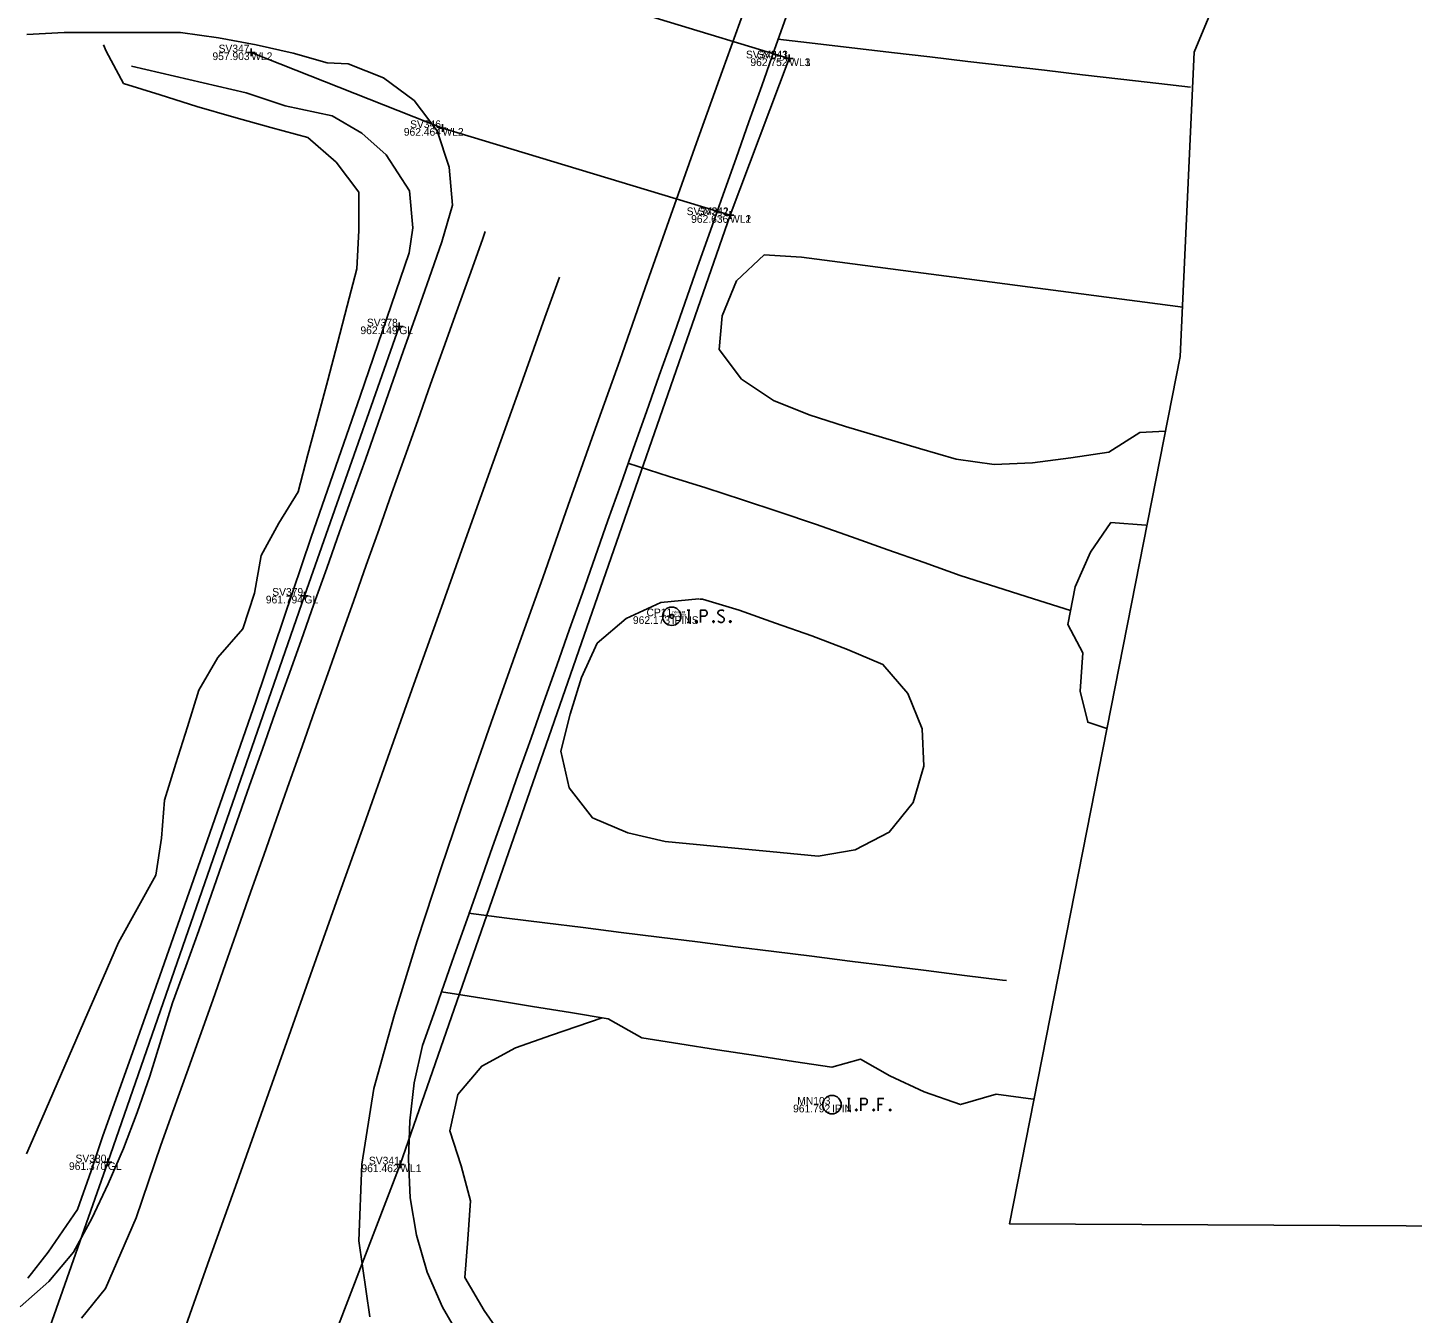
# Model space of a CAD drawing. Extents: x 2262025 to 2264532, y 740981 to 742724.
# Drawn here: x 2263322.3 to 2263502.4, y 742430.2 to 742597.4 of the extents above; entities that cross this region are included whole.
import ezdxf

# ---------------------------------------------------------------- set-up
doc = ezdxf.new("R2010")
doc.units = 0
for name, color, linetype in [('DT_X_Break_Line', 7, 'Continuous'), ('GE_X_Alignment_100_Cardinal_Points', 7, 'Continuous'), ('GE_X_Alignment_100_Curve_Data', 7, 'Continuous'), ('HY_X_Spring_Cells', 7, 'Continuous'), ('PV_X_Driveway', 7, 'Continuous'), ('RS_Raster1', 7, 'Continuous'), ('RW_X_CL', 7, 'Continuous'), ('RW_X_CL_1000_Bearings', 7, 'Continuous'), ('RW_X_CL_1000_Distances', 7, 'Continuous'), ('RW_X_CL_1000_Stations', 7, 'Continuous'), ('RW_X_CL_100_Bearings', 7, 'Continuous'), ('RW_X_CL_100_Cardinal_Points', 7, 'Continuous'), ('RW_X_CL_500_Curve_Data', 7, 'Continuous'), ('SC_Scratch4', 7, 'Continuous'), ('SV_X_Control_Cells_Found', 7, 'Continuous'), ('SV_X_Text_Comment', 7, 'Continuous'), ('SV_X_Text_Elevation', 7, 'Continuous'), ('TopoDOT Temp', 7, 'Continuous'), ('UT_X_Gas', 7, 'Continuous'), ('UT_X_Water', 7, 'Continuous')]:
    doc.layers.add(name, color=color, linetype=linetype)

msp = doc.modelspace()

# ---------------------------------------------------------------- linework, layer by layer
at = {"layer": 'DT_X_Break_Line'}
for points in [[(2263419.9, 742595.91), (2263424.75, 742595.35), (2263434.68, 742594.19), (2263439.65, 742593.62), (2263444.62, 742593.04), (2263449.58, 742592.47), (2263454.55, 742591.89), (2263459.52, 742591.31), (2263464.48, 742590.74), (2263469.45, 742590.16), (2263473.55, 742589.68)], [(2263400.39, 742540.76), (2263405.76, 742539.06), (2263410.53, 742537.55), (2263415.29, 742536.02), (2263420.03, 742534.43), (2263424.77, 742532.84), (2263429.49, 742531.2), (2263434.2, 742529.52), (2263438.91, 742527.84), (2263443.62, 742526.17), (2263448.38, 742524.64), (2263453.15, 742523.13), (2263457.95, 742521.6)], [(2263379.67, 742482.22), (2263384.63, 742481.6), (2263389.59, 742480.98), (2263394.55, 742480.36), (2263399.51, 742479.74), (2263404.47, 742479.11), (2263409.43, 742478.49), (2263414.39, 742477.87), (2263419.35, 742477.25), (2263424.31, 742476.63), (2263429.27, 742476.01), (2263434.24, 742475.39), (2263439.2, 742474.77), (2263444.16, 742474.15), (2263449.12, 742473.52), (2263449.61, 742473.46)]]:
    msp.add_lwpolyline(points, dxfattribs=at)
at = {"layer": 'GE_X_Alignment_100_Cardinal_Points'}
msp.add_lwpolyline([(2263322.32, 742434.75), (2263324.98, 742438.15), (2263328.8, 742443.67), (2263330.57, 742448.73), (2263332.08, 742453.28), (2263335.94, 742464.06), (2263339.49, 742474.09), (2263345.66, 742491.66), (2263351.99, 742509.81), (2263359.2, 742531.16), (2263365.57, 742549.5), (2263371.94, 742568.15), (2263372.4, 742571.39), (2263371.98, 742576.22), (2263368.93, 742580.89), (2263365.76, 742583.71), (2263361.94, 742585.94), (2263355.81, 742587.26), (2263350.72, 742588.96), (2263335.82, 742592.43)], dxfattribs=at)
at = {"layer": 'GE_X_Alignment_100_Curve_Data'}
for points in [[(2263321.32, 742431.03), (2263325.07, 742434.33), (2263328.26, 742438.16), (2263330.65, 742442.54), (2263332.8, 742447.05), (2263334.79, 742451.64), (2263336.54, 742456.32), (2263338.21, 742461.03), (2263339.67, 742465.81), (2263341.16, 742470.59), (2263342.87, 742475.28), (2263344.57, 742479.99), (2263346.22, 742484.71), (2263347.88, 742489.42), (2263349.54, 742494.14), (2263351.19, 742498.86), (2263352.85, 742503.58), (2263354.52, 742508.29), (2263356.2, 742513), (2263357.87, 742517.71), (2263359.55, 742522.42), (2263361.22, 742527.13), (2263362.89, 742531.85), (2263364.57, 742536.56), (2263366.24, 742541.27), (2263367.89, 742545.99), (2263369.55, 742550.7), (2263371.21, 742555.42), (2263372.87, 742560.14), (2263374.52, 742564.86), (2263376.2, 742569.57), (2263377.56, 742574.33), (2263377.13, 742579.29), (2263375.58, 742584), (2263372.59, 742587.94), (2263368.59, 742590.9), (2263364.02, 742592.72), (2263361.27, 742592.87)], [(2263378.8, 742426.67), (2263376.28, 742430.99), (2263374.29, 742435.54), (2263372.9, 742440.34), (2263372.06, 742445.23), (2263371.85, 742450.23), (2263372.01, 742455.21), (2263372.59, 742460.17), (2263373.69, 742465.02), (2263375.34, 742469.74), (2263376.13, 742472.02)]]:
    msp.add_lwpolyline(points, dxfattribs=at)
at = {"layer": 'PV_X_Driveway'}
msp.add_lwpolyline([(2263322.19, 742596.54), (2263327.07, 742596.78), (2263332.18, 742596.78), (2263337.18, 742596.78), (2263342.18, 742596.78), (2263347.13, 742596.12), (2263352.04, 742595.19), (2263356.83, 742594.1), (2263361.27, 742592.87)], dxfattribs=at)
at = {"layer": 'RS_Raster1'}
msp.add_lwpolyline([(2263811.08, 742440.01), (2263450.03, 742441.81), (2263472.22, 742554.63), (2263474.02, 742594.23), (2263511.21, 742683.65), (2263410.45, 742724.45), (2263373.87, 742626.04), (2263193.94, 742588.23), (2263081.19, 742567.23), (2263085.99, 742531.22), (2263114.18, 742392.6), (2262376.34, 742066.06)], dxfattribs=at)
at = {"layer": 'RW_X_CL_1000_Bearings'}
msp.add_line((2263406.09, 742520.86), (2263406.09, 742520.86), dxfattribs=at)
msp.add_line((2263406.09, 742520.86), (2263406.09, 742520.86), dxfattribs=at)
msp.add_line((2263406.09, 742520.86), (2263406.09, 742520.86), dxfattribs=at)
at = {"layer": 'RW_X_CL_1000_Distances'}
for points in [[(2263366.8, 742429.72), (2263365.41, 742439.61), (2263365.76, 742449.58), (2263367.32, 742459.44), (2263370.03, 742469.07), (2263372.98, 742478.62), (2263376.11, 742488.12), (2263379.31, 742497.59), (2263382.6, 742507.04), (2263385.95, 742516.46), (2263389.3, 742525.88), (2263392.63, 742535.31), (2263395.97, 742544.74), (2263399.34, 742554.15), (2263402.64, 742563.59), (2263405.97, 742573.02), (2263409.31, 742582.44), (2263412.71, 742591.85), (2263416.07, 742601.27)], [(2263329.31, 742429.55), (2263332.46, 742433.43), (2263334.44, 742438.03), (2263336.41, 742442.62), (2263338.03, 742447.35), (2263339.65, 742452.08), (2263341.34, 742456.78), (2263343.02, 742461.49), (2263344.7, 742466.2), (2263346.39, 742470.91), (2263348.04, 742475.63), (2263349.7, 742480.34), (2263351.36, 742485.06), (2263353.02, 742489.78), (2263354.67, 742494.49), (2263356.33, 742499.21), (2263358, 742503.92), (2263359.67, 742508.64), (2263361.34, 742513.35), (2263363.01, 742518.06), (2263364.68, 742522.78), (2263366.35, 742527.49), (2263368.02, 742532.2), (2263369.69, 742536.92), (2263371.37, 742541.62), (2263373.05, 742546.33), (2263374.73, 742551.04), (2263376.42, 742555.75), (2263378.1, 742560.46), (2263379.78, 742565.16), (2263381.46, 742569.87), (2263381.84, 742570.92)]]:
    msp.add_lwpolyline(points, dxfattribs=at)
at = {"layer": 'RW_X_CL_1000_Stations'}
msp.add_line((2263406.09, 742520.86), (2263406.09, 742520.86), dxfattribs=at)
msp.add_line((2263406.09, 742520.86), (2263406.09, 742520.86), dxfattribs=at)
msp.add_line((2263406.09, 742520.86), (2263406.09, 742520.86), dxfattribs=at)
msp.add_circle((2263406.09, 742520.86), 0.25, dxfattribs=at)
msp.add_circle((2263406.09, 742520.86), 0.25, dxfattribs=at)
msp.add_circle((2263406.09, 742520.86), 0.25, dxfattribs=at)
at = {"layer": 'RW_X_CL_100_Bearings'}
for points in [[(2263408.11, 742521.67), (2263408.46, 742521.67)], [(2263408.29, 742520.07), (2263408.29, 742521.67)], [(2263409.85, 742520.07), (2263409.85, 742521.67), (2263410.38, 742521.67), (2263410.44, 742521.65), (2263410.51, 742521.63), (2263410.55, 742521.6), (2263410.58, 742521.58), (2263410.62, 742521.51), (2263410.66, 742521.45), (2263410.68, 742521.35), (2263410.68, 742521.2), (2263410.67, 742521.15), (2263410.65, 742521.07), (2263410.6, 742520.99), (2263410.56, 742520.95), (2263410.52, 742520.92), (2263410.47, 742520.9), (2263410.38, 742520.88), (2263409.85, 742520.88)], [(2263412.86, 742521.55), (2263412.84, 742521.58), (2263412.81, 742521.6), (2263412.71, 742521.64), (2263412.59, 742521.67), (2263412.5, 742521.67), (2263412.46, 742521.67), (2263412.32, 742521.63), (2263412.2, 742521.55), (2263412.12, 742521.45), (2263412.1, 742521.35), (2263412.1, 742521.28), (2263412.12, 742521.17), (2263412.21, 742521.09), (2263412.82, 742520.71), (2263412.87, 742520.66), (2263412.89, 742520.61), (2263412.92, 742520.53), (2263412.92, 742520.46), (2263412.91, 742520.38), (2263412.89, 742520.33), (2263412.87, 742520.27), (2263412.85, 742520.22), (2263412.83, 742520.18), (2263412.79, 742520.14), (2263412.76, 742520.12), (2263412.72, 742520.09), (2263412.68, 742520.08), (2263412.59, 742520.07), (2263412.43, 742520.07), (2263412.33, 742520.09), (2263412.19, 742520.18), (2263412.1, 742520.25)], [(2263408.11, 742520.07), (2263408.46, 742520.07)], [(2263409.25, 742520.28), (2263409.3, 742520.28), (2263409.33, 742520.25), (2263409.37, 742520.2), (2263409.37, 742520.14), (2263409.33, 742520.09), (2263409.3, 742520.07), (2263409.25, 742520.07), (2263409.21, 742520.09), (2263409.18, 742520.14), (2263409.18, 742520.2), (2263409.21, 742520.25), (2263409.25, 742520.28)], [(2263411.49, 742520.28), (2263411.55, 742520.28), (2263411.58, 742520.25), (2263411.62, 742520.2), (2263411.62, 742520.14), (2263411.58, 742520.09), (2263411.55, 742520.07), (2263411.49, 742520.07), (2263411.46, 742520.09), (2263411.43, 742520.14), (2263411.43, 742520.2), (2263411.46, 742520.25), (2263411.49, 742520.28)], [(2263413.68, 742520.28), (2263413.73, 742520.28), (2263413.76, 742520.25), (2263413.8, 742520.2), (2263413.8, 742520.14), (2263413.76, 742520.09), (2263413.73, 742520.07), (2263413.68, 742520.07), (2263413.64, 742520.09), (2263413.61, 742520.14), (2263413.61, 742520.2), (2263413.64, 742520.25), (2263413.68, 742520.28)]]:
    msp.add_lwpolyline(points, dxfattribs=at)
msp.add_circle((2263406.09, 742520.86), 1.2, dxfattribs=at)
at = {"layer": 'RW_X_CL_100_Cardinal_Points'}
for p, q in [((2263350.9, 742594.21), (2263351.9, 742594.21)), ((2263351.4, 742594.71), (2263351.4, 742593.71)), ((2263351.4, 742594.21), (2263351.4, 742594.21)), ((2263420.88, 742593.43), (2263421.88, 742593.43)), ((2263420.88, 742593.43), (2263421.88, 742593.43)), ((2263421.38, 742593.93), (2263421.38, 742592.93)), ((2263421.38, 742593.93), (2263421.38, 742592.93)), ((2263421.38, 742593.43), (2263421.38, 742593.43)), ((2263421.38, 742593.43), (2263421.38, 742593.43)), ((2263376.27, 742584.87), (2263376.27, 742583.87)), ((2263375.77, 742584.37), (2263376.77, 742584.37)), ((2263376.27, 742584.37), (2263376.27, 742584.37)), ((2263413.17, 742573.04), (2263414.17, 742573.04)), ((2263413.17, 742573.04), (2263414.17, 742573.04)), ((2263413.67, 742573.54), (2263413.67, 742572.54)), ((2263413.67, 742573.54), (2263413.67, 742572.54)), ((2263413.67, 742573.04), (2263413.67, 742573.04)), ((2263413.67, 742573.04), (2263413.67, 742573.04)), ((2263370.15, 742558.56), (2263371.15, 742558.56)), ((2263370.65, 742559.06), (2263370.65, 742558.06)), ((2263370.65, 742558.56), (2263370.65, 742558.56)), ((2263357.82, 742523.53), (2263358.82, 742523.53)), ((2263358.32, 742524.03), (2263358.32, 742523.03)), ((2263358.32, 742523.53), (2263358.32, 742523.53)), ((2263332.25, 742449.83), (2263333.25, 742449.83)), ((2263332.75, 742450.33), (2263332.75, 742449.33)), ((2263332.75, 742449.83), (2263332.75, 742449.83)), ((2263370.28, 742449.55), (2263371.28, 742449.55)), ((2263370.78, 742450.05), (2263370.78, 742449.05)), ((2263370.78, 742449.55), (2263370.78, 742449.55))]:
    msp.add_line(p, q, dxfattribs=at)
at = {"layer": 'RW_X_CL_500_Curve_Data'}
for points in [[(2263376.13, 742472.02), (2263377.79, 742476.74), (2263379.46, 742481.45), (2263381.13, 742486.16), (2263382.79, 742490.88), (2263384.46, 742495.59), (2263386.13, 742500.31), (2263387.79, 742505.02), (2263389.46, 742509.73), (2263391.13, 742514.45), (2263392.79, 742519.16), (2263394.46, 742523.88), (2263396.13, 742528.59), (2263397.79, 742533.3), (2263399.46, 742538.02), (2263401.13, 742542.73), (2263402.79, 742547.45), (2263404.46, 742552.16), (2263406.13, 742556.87), (2263407.79, 742561.59), (2263409.46, 742566.3), (2263411.13, 742571.02), (2263412.79, 742575.73), (2263414.46, 742580.44), (2263416.13, 742585.16), (2263417.79, 742589.87), (2263419.46, 742594.59), (2263421.13, 742599.3)], [(2263472.55, 742561.07), (2263467.6, 742561.72), (2263462.64, 742562.37), (2263457.68, 742563.03), (2263452.72, 742563.68), (2263447.77, 742564.33), (2263442.81, 742564.98), (2263437.85, 742565.63), (2263432.89, 742566.28), (2263427.94, 742566.93), (2263422.98, 742567.58), (2263418.11, 742567.87), (2263414.51, 742564.51), (2263412.66, 742559.94), (2263412.24, 742555.55), (2263415.17, 742551.72), (2263419.31, 742548.94), (2263423.95, 742547.07), (2263428.71, 742545.54), (2263433.5, 742544.12), (2263438.3, 742542.7), (2263443.09, 742541.29), (2263448.04, 742540.61), (2263453.03, 742540.8), (2263457.98, 742541.45), (2263462.92, 742542.22), (2263466.98, 742544.76), (2263470.26, 742544.92)], [(2263467.76, 742532.7), (2263463.22, 742533.06), (2263460.57, 742529.2), (2263458.56, 742524.7), (2263457.6, 742519.8), (2263459.57, 742516.12), (2263459.19, 742511.13), (2263460.2, 742507.08), (2263462.7, 742506.28)], [(2263409.61, 742523.11), (2263404.66, 742522.66), (2263400.17, 742520.59), (2263396.37, 742517.34), (2263394.35, 742512.91), (2263392.88, 742508.13), (2263391.65, 742503.29), (2263392.75, 742498.54), (2263395.8, 742494.66), (2263400.37, 742492.67), (2263405.24, 742491.58), (2263410.22, 742491.09), (2263415.19, 742490.61), (2263420.17, 742490.14), (2263425.15, 742489.66), (2263429.94, 742490.48), (2263434.38, 742492.76), (2263437.48, 742496.63), (2263438.89, 742501.38), (2263438.67, 742506.21), (2263436.8, 742510.81), (2263433.56, 742514.59), (2263428.96, 742516.54), (2263424.29, 742518.32), (2263419.57, 742519.98), (2263414.86, 742521.65), (2263410.1, 742523.07), (2263409.71, 742523.07)], [(2263453.11, 742458.03), (2263448.27, 742458.71), (2263443.66, 742457.33), (2263438.94, 742458.99), (2263434.45, 742461.08), (2263430.64, 742463.26), (2263426.89, 742462.19), (2263421.94, 742462.95), (2263417, 742463.71), (2263412.06, 742464.47), (2263407.12, 742465.22), (2263402.19, 742466.02), (2263397.84, 742468.49), (2263392.91, 742469.3), (2263387.97, 742470.1), (2263383.04, 742470.9), (2263378.1, 742471.7), (2263376.13, 742472.02)]]:
    msp.add_lwpolyline(points, dxfattribs=at)
at = {"layer": 'SC_Scratch4'}
msp.add_lwpolyline([(2263339.28, 742418.41), (2263342.63, 742427.83), (2263345.98, 742437.26), (2263349.34, 742446.68), (2263352.69, 742456.1), (2263356.04, 742465.52), (2263359.38, 742474.95), (2263362.72, 742484.37), (2263366.07, 742493.79), (2263369.41, 742503.22), (2263372.77, 742512.64), (2263376.13, 742522.05), (2263379.5, 742531.47), (2263382.86, 742540.89), (2263386.23, 742550.3), (2263389.6, 742559.72), (2263391.48, 742564.96)], dxfattribs=at)
at = {"layer": 'SV_X_Control_Cells_Found'}
for points in [[(2263322.16, 742450.92), (2263324.15, 742455.5), (2263326.15, 742460.09), (2263328.15, 742464.67), (2263330.14, 742469.26), (2263332.14, 742473.84), (2263334.15, 742478.42), (2263338.98, 742487.17), (2263339.74, 742491.98), (2263340.1, 742496.92), (2263341.6, 742501.69), (2263343.09, 742506.47), (2263344.59, 742511.24), (2263347.03, 742515.48), (2263350.32, 742519.24), (2263351.83, 742523.85), (2263352.69, 742528.78), (2263354.98, 742532.95), (2263357.48, 742537.06), (2263358.77, 742541.9), (2263360.05, 742546.73), (2263361.34, 742551.56), (2263362.61, 742556.39), (2263363.88, 742561.23), (2263365.15, 742566.07), (2263365.38, 742571.04), (2263365.38, 742576.04), (2263362.43, 742579.93), (2263358.77, 742583.12), (2263353.96, 742584.45), (2263349.14, 742585.79), (2263344.34, 742587.18), (2263339.56, 742588.67), (2263334.79, 742590.17), (2263332.52, 742594.39), (2263332.18, 742595.21)], [(2263384.54, 742426.44), (2263381.67, 742430.54), (2263379.18, 742434.83), (2263379.55, 742439.82), (2263379.93, 742444.8), (2263378.72, 742449.37), (2263377.21, 742453.91), (2263378.25, 742458.63), (2263381.37, 742462.35), (2263385.75, 742464.73), (2263390.47, 742466.38), (2263397.02, 742468.64)]]:
    msp.add_lwpolyline(points, dxfattribs=at)
at = {"layer": 'SV_X_Text_Elevation'}
for points in [[(2263428.94, 742458.13), (2263429.29, 742458.13)], [(2263428.94, 742456.53), (2263429.29, 742456.53)], [(2263429.12, 742456.53), (2263429.12, 742458.13)], [(2263430.08, 742456.75), (2263430.13, 742456.75), (2263430.17, 742456.72), (2263430.2, 742456.67), (2263430.2, 742456.61), (2263430.17, 742456.56), (2263430.13, 742456.53), (2263430.08, 742456.53), (2263430.04, 742456.56), (2263430.01, 742456.61), (2263430.01, 742456.67), (2263430.04, 742456.72), (2263430.08, 742456.75)], [(2263430.68, 742456.53), (2263430.68, 742458.13), (2263431.21, 742458.13), (2263431.27, 742458.12), (2263431.34, 742458.09), (2263431.38, 742458.07), (2263431.41, 742458.04), (2263431.45, 742457.98), (2263431.49, 742457.92), (2263431.51, 742457.82), (2263431.51, 742457.66), (2263431.5, 742457.61), (2263431.48, 742457.54), (2263431.43, 742457.45), (2263431.39, 742457.41), (2263431.36, 742457.39), (2263431.3, 742457.36), (2263431.21, 742457.35), (2263430.68, 742457.35)], [(2263432.33, 742456.75), (2263432.38, 742456.75), (2263432.41, 742456.72), (2263432.45, 742456.67), (2263432.45, 742456.61), (2263432.41, 742456.56), (2263432.38, 742456.53), (2263432.33, 742456.53), (2263432.29, 742456.56), (2263432.26, 742456.61), (2263432.26, 742456.67), (2263432.29, 742456.72), (2263432.33, 742456.75)], [(2263433.69, 742458.13), (2263432.93, 742458.13), (2263432.93, 742456.53)], [(2263432.93, 742457.35), (2263433.47, 742457.35)], [(2263434.47, 742456.75), (2263434.53, 742456.75), (2263434.56, 742456.72), (2263434.6, 742456.67), (2263434.6, 742456.61), (2263434.56, 742456.56), (2263434.53, 742456.53), (2263434.47, 742456.53), (2263434.44, 742456.56), (2263434.41, 742456.61), (2263434.41, 742456.67), (2263434.44, 742456.72), (2263434.47, 742456.75)]]:
    msp.add_lwpolyline(points, dxfattribs=at)
msp.add_circle((2263426.93, 742457.33), 1.2, dxfattribs=at)
at = {"layer": 'TopoDOT Temp'}
for p, q in [((2263419.9, 742595.91), (2263419.9, 742595.91)), ((2263419.9, 742595.91), (2263419.9, 742595.91)), ((2263424.86, 742595.33), (2263424.86, 742595.33)), ((2263424.86, 742595.33), (2263424.86, 742595.33)), ((2263429.83, 742594.76), (2263429.83, 742594.76)), ((2263429.83, 742594.76), (2263429.83, 742594.76)), ((2263434.8, 742594.18), (2263434.8, 742594.18)), ((2263434.8, 742594.18), (2263434.8, 742594.18)), ((2263439.76, 742593.61), (2263439.76, 742593.61)), ((2263439.76, 742593.61), (2263439.76, 742593.61)), ((2263444.73, 742593.03), (2263444.73, 742593.03)), ((2263444.73, 742593.03), (2263444.73, 742593.03)), ((2263449.7, 742592.45), (2263449.7, 742592.45)), ((2263449.7, 742592.45), (2263449.7, 742592.45)), ((2263454.66, 742591.88), (2263454.66, 742591.88)), ((2263454.66, 742591.88), (2263454.66, 742591.88)), ((2263459.63, 742591.3), (2263459.63, 742591.3)), ((2263459.63, 742591.3), (2263459.63, 742591.3)), ((2263464.59, 742590.72), (2263464.59, 742590.72)), ((2263464.59, 742590.72), (2263464.59, 742590.72)), ((2263469.56, 742590.15), (2263469.56, 742590.15)), ((2263469.56, 742590.15), (2263469.56, 742590.15)), ((2263473.55, 742589.68), (2263473.55, 742589.68)), ((2263473.55, 742589.68), (2263473.55, 742589.68))]:
    msp.add_line(p, q, dxfattribs=at)
at = {"layer": 'UT_X_Gas'}
msp.add_lwpolyline([(2263370.65, 742558.56), (2263358.32, 742523.53), (2263332.75, 742449.83), (2263131.85, 741878.34), (2263108.26, 741811.62)], dxfattribs=at)
at = {"layer": 'UT_X_Water'}
for points in [[(2263421.38, 742593.43), (2263387.64, 742603.7), (2263352.64, 742610.25)], [(2263058.18, 741572.97), (2263085.82, 741651.25), (2263095.93, 741679.99), (2263097.95, 741685.82), (2263106.82, 741712.78), (2263147.36, 741828.66), (2263178.07, 741920.18), (2263217.98, 742032.49), (2263252.6, 742127.99), (2263295.63, 742247.6), (2263334.95, 742356.22), (2263370.78, 742449.55), (2263413.67, 742573.04), (2263421.38, 742593.43)], [(2263413.67, 742573.04), (2263376.27, 742584.37), (2263351.4, 742594.21)]]:
    msp.add_lwpolyline(points, dxfattribs=at)

# ---------------------------------------------------------------- texts
at = {"layer": 'HY_X_Spring_Cells'}
for s, p in [('957.903', (2263346.35, 742593.21)), ('962.752', (2263416.32, 742592.43)), ('962.752', (2263416.32, 742592.43)), ('962.464', (2263371.24, 742583.37)), ('962.636', (2263408.61, 742572.04)), ('962.636', (2263408.61, 742572.04)), ('962.149', (2263365.6, 742557.56)), ('961.794', (2263353.29, 742522.53)), ('962.173', (2263401.04, 742519.86)), ('961.792', (2263421.87, 742456.33)), ('961.370', (2263327.69, 742448.83)), ('961.462', (2263365.73, 742448.55))]:
    msp.add_text(s, height=1, dxfattribs=at).set_placement(p)
at = {"layer": 'RW_X_CL'}
for s, p in [('WL2', (2263351.4, 742593.21)), ('WL3', (2263421.38, 742592.43)), ('WL1', (2263421.38, 742592.43)), ('WL2', (2263376.27, 742583.37)), ('WL2', (2263413.67, 742572.04)), ('WL1', (2263413.67, 742572.04)), ('GL', (2263370.65, 742557.56)), ('GL', (2263358.32, 742522.53)), ('IPINS', (2263406.09, 742519.86)), ('IPIN', (2263426.93, 742456.33)), ('GL', (2263332.75, 742448.83)), ('WL1', (2263370.78, 742448.55))]:
    msp.add_text(s, height=1, dxfattribs=at).set_placement(p)
at = {"layer": 'RW_X_CL_1000_Stations'}
for s, p in [('Index: 52', (2263406.09, 742521.26)), ('Index: 61', (2263406.09, 742521.26)), ('Index: 70', (2263406.09, 742521.26)), ('ΔZ: -0.091', (2263406.09, 742520.86)), ('ΔZ: -0.091', (2263406.09, 742520.86)), ('ΔZ: -0.091', (2263406.09, 742520.86))]:
    msp.add_text(s, height=0.3, dxfattribs=at).set_placement(p)
at = {"layer": 'SV_X_Text_Comment'}
for s, p in [('SV347', (2263347.15, 742594.21)), ('SV343_1', (2263415.74, 742593.43)), ('SV343', (2263417.18, 742593.43)), ('SV346', (2263372.06, 742584.37)), ('SV342_1', (2263408.03, 742573.04)), ('SV342', (2263409.47, 742573.04)), ('SV378', (2263366.44, 742558.56)), ('SV379', (2263354.13, 742523.53)), ('CP11', (2263402.81, 742520.86)), ('MN103', (2263422.42, 742457.33)), ('SV380', (2263328.54, 742449.83)), ('SV341', (2263366.7, 742449.55))]:
    msp.add_text(s, height=1, dxfattribs=at).set_placement(p)

doc.saveas('drawing.dxf')
